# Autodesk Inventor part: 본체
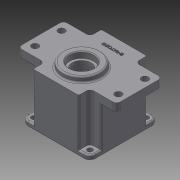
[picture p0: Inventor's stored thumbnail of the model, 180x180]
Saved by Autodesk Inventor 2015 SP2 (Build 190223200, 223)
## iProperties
Created: 2015-06
Part Number: 본체
Material: 일반
Document SubType Name: Modeling
Designer: AMC
Density: 1 g/cm^3
Appearance: 기본값
Author: AMC
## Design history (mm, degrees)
sketch "스케치1"
  geometry: L1 (-45, 45)-(45, 45); L2 (45, 45)-(45, -45); L3 (45, -45)-(-45, -45); L4 (-45, -45)-(-45, 45); 3 further points
  constraints: 8 end point, 2 midpoint, 2 parallel, 1 horizontal, 1 horizontal alignment, 1 perpendicular, 1 vertical alignment
  dimensions: "d0" = 90 distance of L2.end L3.end; "d1" = 90 distance of L1.end L2.end
extrude "돌출1" new body sketch "스케치1" distance "d2" = 70; taper "d3" = 0 deg
sketch "스케치2"
  geometry: L1 (-65, 30)-(65, 30); L2 (65, 30)-(65, -30); L3 (65, -30)-(-65, -30); L4 (-65, -30)-(-65, 30); 3 further points
  constraints: 8 end point, 2 midpoint, 2 parallel, 1 horizontal, 1 horizontal alignment, 1 perpendicular, 1 vertical alignment
  dimensions: "d4" = 60 distance between parallel lines of L3 L1; "d5" = 130 distance between parallel lines of L2 L4
extrude "돌출2" join sketch "스케치2" distance "d6" = 12; taper "d7" = 0 deg
sketch "스케치3"
  geometry: C1 r 25 at (0, -11); 1 further point
  constraints: 1 centre point, 1 vertical alignment
  dimensions: "d8" = 50 diameter of C1; "d9" = 11 distance of point (0, 0) C1.centre
extrude "돌출3" join sketch "스케치3" distance "d10" = 7; taper "d11" = 0 deg
sketch "스케치4"
  geometry: C1 r 40 at (0, 0); 1 further point
  constraints: 1 centre point, 1 coincident
  dimensions: "d12" = 80 diameter of C1
extrude "돌출4" cut sketch "스케치4" distance "d13" = 9; taper "d14" = 0 deg
sketch "스케치5"
  geometry: C1 r 39 at (0, 0); 1 further point
  constraints: 1 centre point, 1 coincident
  dimensions: "d15" = 78 diameter of C1
extrude "돌출5" cut sketch "스케치5" distance "d16" = 52; taper "d17" = 0 deg
sketch "스케치6"
  geometry: L1 (0, 0)-(0, -10.322); L2 (0, 0)-(24.749, -24.749); C1 r 39 at (0, 0) reference; C2 r 4 at (24.749, -24.749)
  constraints: 4 end point, 1 centre point, 1 coincident, 1 vertical
  dimensions: "d18" = 45 deg angle of L1 L2; "d19" = 35 distance of L1.start L2.end; "d23" = 8 diameter of C2
extrude "돌출6" join sketch "스케치6" distance "d24" = 52; taper "d25" = 0 deg
sketch "스케치7"
  geometry: L1 (-0.145, -5.511)-(-2.828, -2.828); L2 (-24.749, 24.749)-(-24.749, 16.128); L3 (-24.749, 24.749)-(-14.182, 24.749); L4 (5.511, 0.145)-(2.828, 2.828); A1 r 39 centre (-24.749, 24.749) between (2.828, -2.828) and (5.511, 0.145) reference; A2 r 4 centre (0, 0) between (2.828, -2.828) and (2.828, 2.828) reference; 1 further point
  constraints: 8 end point, 4 point on circle, 2 tangent, 1 horizontal, 1 vertical
  dimensions: "d27" = 45 deg angle of L2 L1; "d28" = 45 deg angle of L3 L4
extrude "돌출7" join sketch "스케치7" distance "d29" = 52; taper "d30" = 0 deg
sketch "스케치8"
  geometry: C1 r 20.5 at (0, -11); C2 r 14 at (0, 20); 1 further point
  constraints: 2 centre point, 2 vertical alignment
  dimensions: "d34" = 41 diameter of C1; "d35" = 28 diameter of C2; "d36" = 11 distance of point (0, 0) C1.centre; "d37" = 20 distance of C2.centre point (0, 0)
extrude "돌출8" join sketch "스케치8" distance "d38" = 7; taper "d39" = 0 deg
hole "구멍1" diameter "d42" = 25; stored, may be unused: countersink angle "d46" = 90 deg, drill point angle "d48" = 118 deg; dims "d43" = 6, "d44" = 32, "d45" = 8, "d47" = 8, "d58" = 10, "d59" = 10
hole "구멍2" diameter "d51" = 25; stored, may be unused: countersink angle "d55" = 90 deg, drill point angle "d57" = 118 deg; dims "d52" = 6, "d53" = 35, "d54" = 10, "d56" = 8, "d60" = 10, "d61" = 10
hole "구멍3" diameter "d64" = 19; stored, may be unused: countersink angle "d68" = 90 deg, drill point angle "d70" = 0 deg; dims "d65" = 6, "d66" = 22, "d67" = 7, "d69" = 8, "d71" = 10, "d72" = 10
fillet "모깎기1" dims "d73" = 5
sketch "스케치10"
  geometry: C1 r 4.5 at (55, 17.5); C2 r 4.5 at (55, -17.5); 2 further points
  constraints: 2 centre point, 1 coincident
  dimensions: "d74" = 55 horizontal distance of point (0, 0) point (55, 17.5); "d75" = 17.5 vertical distance of point (0, 0) point (55, 17.5); "d76" = 9 diameter of C1; "d77" = 9 diameter of C2; "d78" = 55 horizontal distance of point (0, 0) C2.centre; "d79" = 17.5 vertical distance of point (0, 0) C2.centre
extrude "돌출9" cut sketch "스케치10" stored distance "d80" = 7; taper "d81" = 0 deg
fillet "모깎기2" dims "d82" = 8
sketch "스케치11"
  geometry: L1 (37, -45)-(-37, -45) reference; L2 (45, -30)-(30, -30); L3 (30, -30)-(30, -45); L4 (30, -45)-(45, -45); L5 (45, -45)-(45, -30); 1 further point
  constraints: 8 end point, 2 parallel, 1 horizontal, 1 perpendicular, 1 point on line
  dimensions: "d83" = 30 distance from line of point (0, 0) L3
extrude "돌출10" cut sketch "스케치11" distance "d84" = 63; taper "d85" = 0 deg
fillet "모깎기3" dims "d86" = 5
sketch "스케치13"
  geometry: C1 r 3.5 at (37, -37); C2 r 3.5 at (37, 37); C3 r 3.5 at (-37, -37); C4 r 3.5 at (-37, 37); A1 r 8 centre (37, -37) between (37, -45) and (45, -37) reference; A2 r 8 centre (-37, -37) between (-45, -37) and (-37, -45) reference; A3 r 8 centre (-37, 37) between (-37, 45) and (-45, 37) reference; A4 r 8 centre (37, 37) between (45, 37) and (37, 45) reference; 1 further point
  constraints: 4 centre point, 4 coincident
  dimensions: "d87" = 7 diameter of C1; "d88" = 7 diameter of C2; "d89" = 7 diameter of C3; "d90" = 7 diameter of C4
extrude "돌출11" cut sketch "스케치13" distance "d91" = 63; taper "d92" = 0 deg
sketch "스케치14"
  geometry: A1 r 4 centre (24.749, -24.749) between (27.577, -21.92) and (21.92, -27.577) reference; 3 further points
hole "구멍4" sketch "스케치14" at (24.749, -24.749) diameter "d94" = 3.459; stored, may be unused: countersink angle "d98" = 90 deg, drill point angle "d100" = 118 deg; dims "d95" = 12, "d96" = 22, "d97" = 7, "d99" = 15
fillet "모깎기5" dims "d104" = 0.3
fillet "모깎기6" dims "d105" = 2
fillet "모깎기7" dims "d106" = 3
fillet "모깎기8" dims "d107" = 3.5
fillet "모깎기9" dims "d108" = 2
fillet "모깎기10" dims "d109" = 2
fillet "모깎기11" dims "d110" = 2
fillet "모깎기12" dims "d111" = 2
fillet "모깎기13" dims "d112" = 2
fillet "모깎기14" dims "d113" = 2
fillet "모깎기15" dims "d114" = 2
chamfer "모따기1" distance "d115" = 1; stored, may be unused: second distance "d116" = 2, angle "d117" = 45 deg
sketch "스케치15"
  geometry: L1 (28, 45)-(-28, 45) reference; 2 further points
  constraints: 1 vertical alignment, 1 other
  dimensions: "d118" = 15 distance from line of L1 point (0, 30)
feature "엠보싱1" sketch "스케치15" dims "d119" = 0.5, "d120" = 0
fillet "모깎기16" dims "d121" = 2
node "솔리드1"
pattern_circular "원형 패턴1" dims angle "d32" = 360 deg
mirror "대칭1"
mirror "대칭2"
mirror "대칭3"
pattern_circular "원형 패턴2" dims angle "d102" = 360 deg
node "작업 평면1"
